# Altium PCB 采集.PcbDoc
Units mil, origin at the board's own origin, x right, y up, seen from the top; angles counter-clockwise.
Board outline 2385 x 1960 mil, 2 copper layers (Top Layer, Bottom Layer); 59 components, 37 nets, 212 pads, 27 vias.
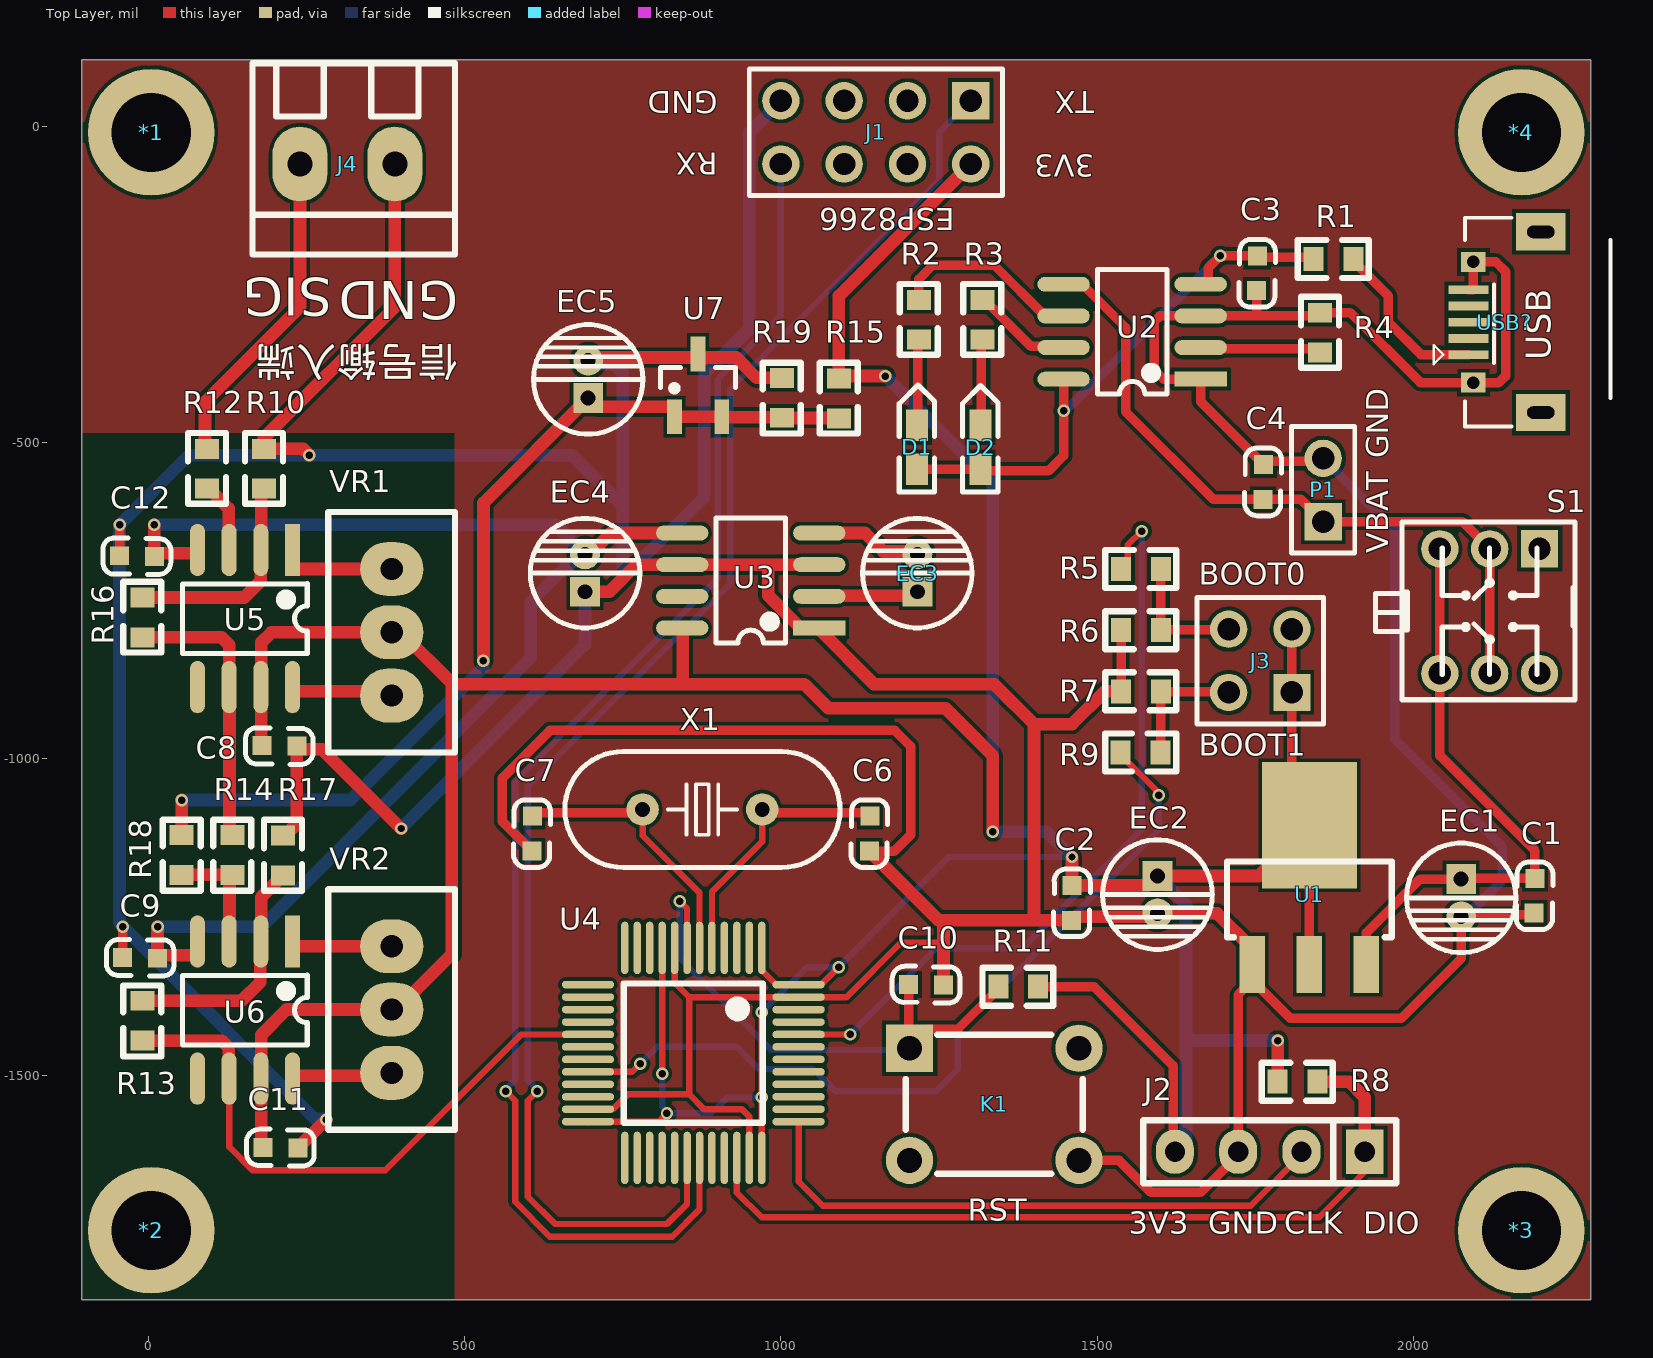
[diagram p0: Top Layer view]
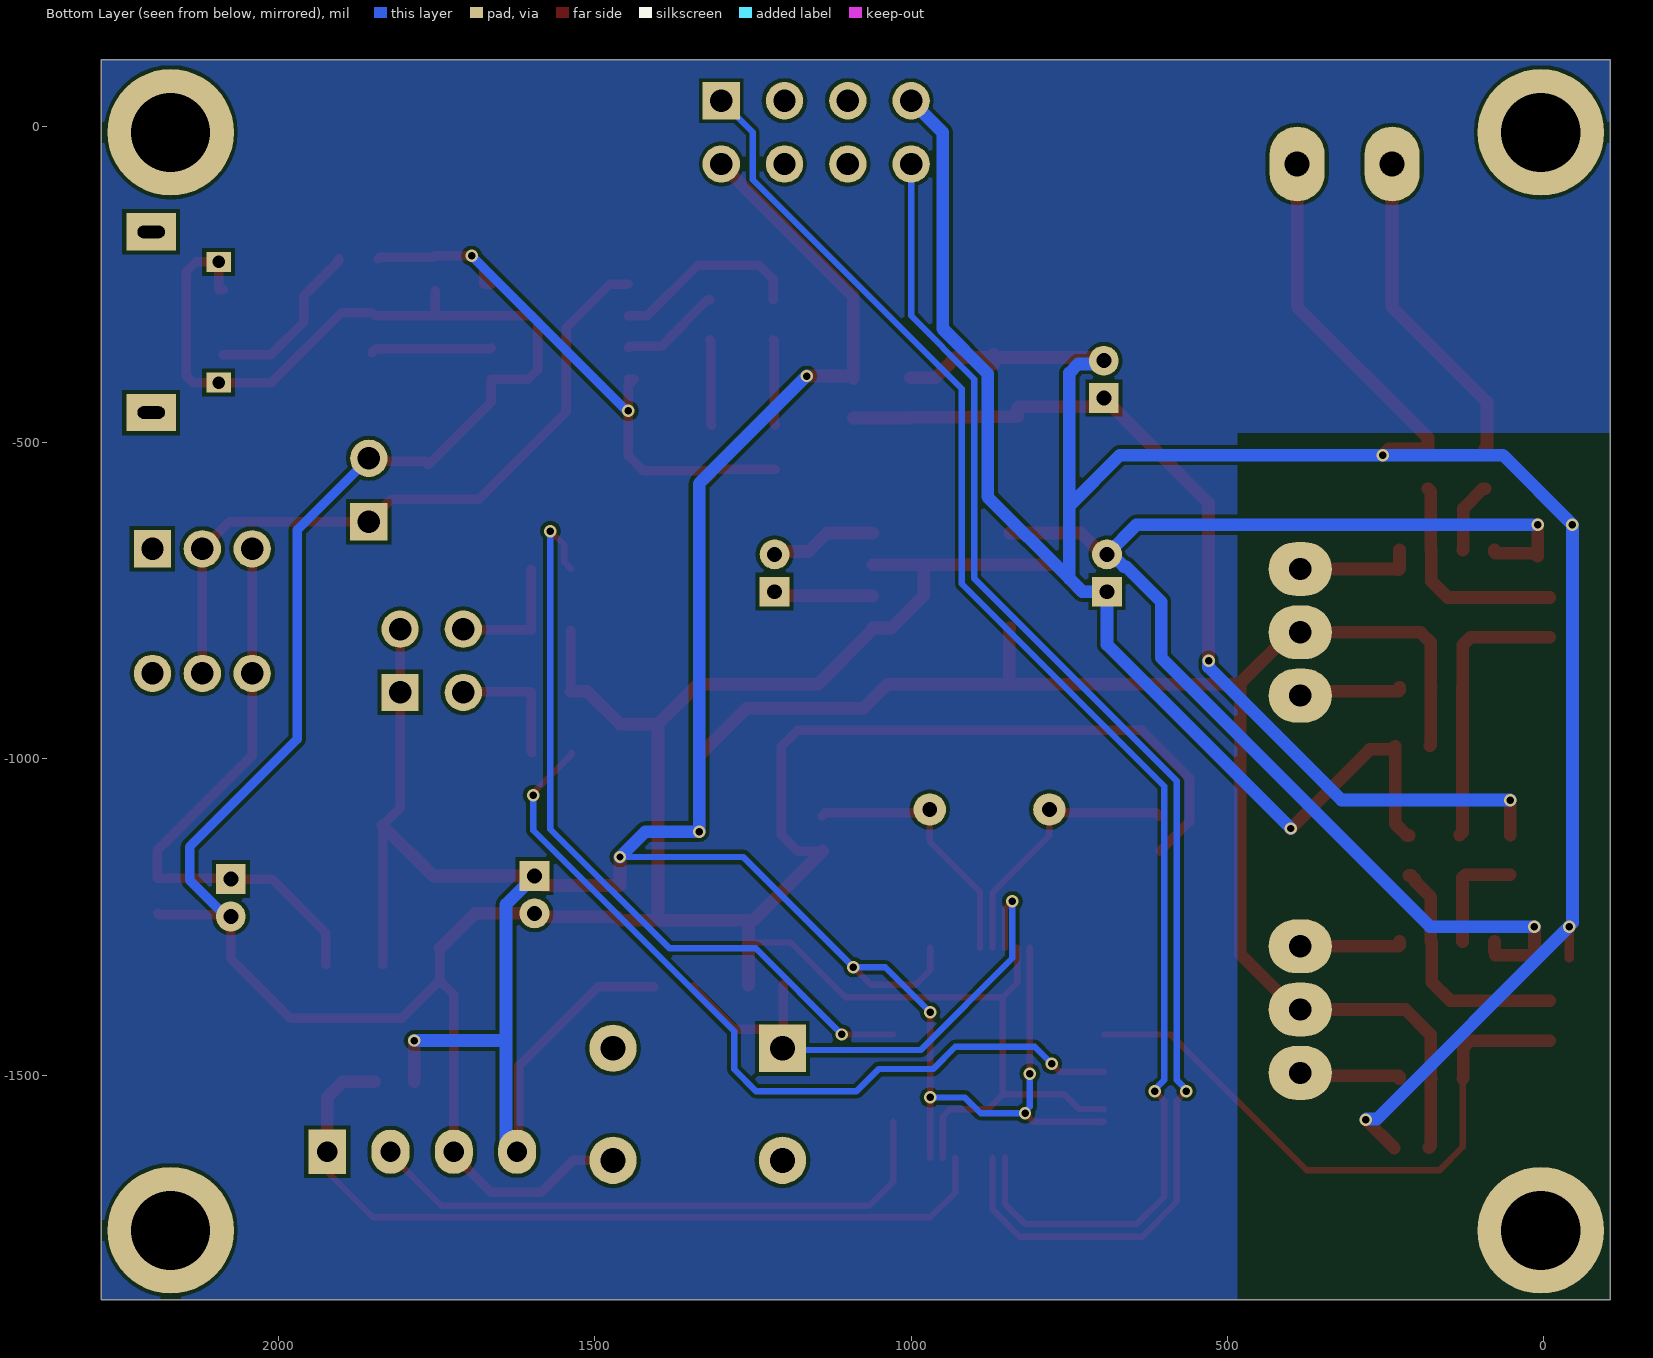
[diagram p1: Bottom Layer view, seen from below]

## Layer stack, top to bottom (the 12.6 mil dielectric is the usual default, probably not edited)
Top Solder: solder mask 0.4, Solder Resist, Dk 3.5
Top Layer: signal copper 1.4
Dielectric 1: dielectric 12.6, FR-4, Dk 4.8
Bottom Layer: signal copper 1.4
Bottom Solder: solder mask 0.4, Solder Resist, Dk 3.5

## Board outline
-105,-1855 2280,-1855 2280,105 -105,105

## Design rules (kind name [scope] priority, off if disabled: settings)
Clearance [All] p1: gap=6 ignorepadtopadclearanceinfootprint=FALSE except(0: Arc-Hole Track-Hole SMDPad-Hole THPad-Hole Via-Hole Fill-Hole Poly-Hole Region-Hole Text-Hole)
PolygonConnect [All] p1: connectstyle=Relief reliefconductorwidth=10 reliefentries=4 polygonreliefangle="90 Angle" airgapwidth=10
RoutingVias [All] p1: holewidth=28 width=50 viastyle="Through Hole" minholewidth=28 minwidth=50 maxholewidth=28 maxwidth=50
SolderMaskExpansion [All] p1: expansion=4
Width [All] p1: maxlimit=60 minlimit=10 preferedwidth=10 minimp=50.000000 maximp=50.000000 favimp=50.000000
30 further rules are at their usual default settings.

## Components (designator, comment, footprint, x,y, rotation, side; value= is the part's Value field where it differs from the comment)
*1 "*" "M3 125X200" 5,-10 r0 top
*2 "*" "M3 125X200" 5,-1745 r0 top
*3 "*" "M3 125X200" 2170,-1745 r0 top
*4 "*" "M3 125X200" 2170,-10 r0 top
C1 "CAP" 0603C 2190,-1244.06 r90 top
C2 "CAP" 0603C 1458.65,-1255.21 r90 top
C3 "106" 0603C 1751.4,-260.21 r90 top
C4 "106" 0603C 1763.11,-534.79 r270 top
C6 "22pf" 0603C 1141.02,-1090.39 r270 top
C7 "22pf" 0603C 607.93,-1090.39 r270 top
C8 "CAP" 0603C 179.79,-978.65 r0 top
C9 "CAP" 0603C 15.21,-1315.35 r180 top
C10 "100nf" 0603C 1257.06,-1357.9 r180 top
C11 "CAP" 0603C 236.79,-1615.51 r180 top
C12 "CAP" 0603C -45.21,-678.64 r0 top
D1 "LED" LED-0603G 1215.24,-542.58 r90 top
D2 "RLED" LED-0603Y 1315.24,-542.58 r90 top
EC1 "10uf" DIP-EC1.5X4X8 2075,-1190 r270 top
EC2 "10uf" DIP-EC1.5X4X8 1595,-1185 r270 top
EC3 "10uf" DIP-EC1.5X4X8 1215.55,-735.85 r90 top
EC4 "10uf" DIP-EC1.5X4X8 690.55,-735.85 r90 top
EC5 "4.7uf" DIP-EC1.5X4X8 695.55,-429.89 r90 top
J1 "*" Fe-HDR2X4/2.54-S 1300,40 r180 top
J2 "Pin HDR1X4" "Pin HDR1X4/2.54mm-S" 1922.57,-1620.76 r270 top
J3 "Pin HDR2X2" "Pin HDR2X2/2.54mm-S" 1807.54,-895 r90 top
J4 "*" KF128-3.81-2P 390,-60 r180 top
K1 "KEY" DIP-6X6X5 1203.27,-1457.19 r0 top
P1 "Header 2" HDR1X2 1856.76,-625 r90 top
R1 "1R" 0603R 1841.76,-210 r0 top
R2 "5K" 0603R 1217.99,-274.58 r270 top
R3 "5K" 0603R 1318.24,-274.58 r270 top
R4 "5K" 0603R 1851.76,-295 r270 top
R5 "10k" 0603R 1537.57,-700 r0 top
R6 "10k" 0603R 1537.57,-796.67 r0 top
R7 "10k" 0603R 1537.57,-893.33 r0 top
R8 "10k" 0603R 1785,-1510 r0 top
R9 "10k" 0603R 1599.57,-990 r180 top
R10 "20k" 0603R 183.15,-510 r270 top
R11 "10k" 0603R 1343.58,-1360 r0 top
R12 "49.9" 0603R 93.15,-510 r270 top
R13 "20k" 0603R -8.91,-1445.16 r90 top
R14 "20k" 0603R 133.15,-1183.15 r90 top
R15 "49.9" 0603R 1091.57,-398.91 r270 top
R16 "180k" 0603R -8.91,-745 r270 top
R17 "20k" 0603R 213.15,-1121.15 r270 top
R18 "20k" 0603R 53.15,-1183.15 r90 top
R19 "3k" 0603R 1001.57,-460.91 r90 top
S1 "KFT DIP-7X7" "KFT DIP-7X7" 2198.74,-668.15 r270 top
U1 "AMS1117" SOT223 1835,-1325 r0 top
U2 "TP4056X" SOP8 1663.29,-400 r180 top
U3 "tp7660" SOP8 1060.55,-793.13 r180 top
U4 "STM32F103C8T6" "LQFP48 7X7" 861.57,-1465 r180 top
U5 "OP07CDR" SOP8 228.15,-670 r270 top
U6 "OP07CDR" SOP8 228.15,-1288.62 r270 top
U7 "TL431_SMD" SOT23 831.77,-459.35 r0 top
USB? "Micro-USB" USB-micro_B 2086.57,-361.18 r90 top
VR1 "20k" 3296W 385,-800 r270 top
VR2 "20k" 3296W 385,-1396.1 r90 top
X1 "XTAL-2P" "OSC HC-49S" 876.06,-1080 r0 top

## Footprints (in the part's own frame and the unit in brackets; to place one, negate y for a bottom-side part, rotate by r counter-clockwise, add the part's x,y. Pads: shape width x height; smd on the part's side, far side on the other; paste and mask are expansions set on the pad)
0603C [mil]
  rect 30x30 smd: 1(0.21,-0.35) 2(55.21,-1.35)
  silkscreen extent -26,-30 81,28, body extent -1,-15 62,17, height 12
0603R [mm]
  rect 0.8x0.965 smd: 1(0,0) 2(1.6,0)
  silkscreen extent -0.63,-0.76 2.21,0.76, body extent -0.04,-0.41 1.56,0.41, height 0.45
3296W [mil]
  oval 85x100 hole 35: 1(-100,0) 2(0,0) 3(100,0)
  silkscreen extent -190,-100 190,100, body extent -188,-94 188,94, height 455
DIP-6X6X5 [mm]
  rect 1.9x1.9 hole 1: 1(0,0)
  round 1.9 hole 1: 2(0,-4.5) 3(6.8,-4.5) 4(6.8,0)
  silkscreen extent -0.16,-5.04 6.96,0.54, body extent -0.8,-5.24 7.41,0.76, height 4.95
DIP-EC1.5X4X8 [mm]
  rect 1.2x1.2 hole 0.6: 1(0,0)
  round 1.2 hole 0.6: 2(1.5,0)
  silkscreen extent -1.45,-2.2 2.95,2.2, body extent -1.26,-1.97 2.76,2.03, height 8.04
Fe-HDR2X4/2.54-S [mm] "Connector; Header; 4x2 Position"
  rect 1.5x1.5 hole 0.9: 1(0,0)
  round 1.5 hole 0.9: 2(0,2.54) 3(2.54,0) 4(2.54,2.54) 5(5.08,0) 6(5.08,2.54) 7(7.62,0) 8(7.62,2.54)
  silkscreen extent -1.27,-1.27 8.89,3.81, body extent -1.27,-1.23 9.14,3.77, height 8.5
HDR1X2 [mm] "Connector; Header; 2 Position"
  rect 1.5x1.5 hole 0.9: 1(0,0)
  round 1.5 hole 0.9: 2(2.54,0)
  silkscreen extent -1.27,-1.27 3.81,1.27
KF128-3.81-2P [mm] "螺钉式接线端子，脚距3.81mm"
  oval 2.2x3 hole 1: 1(0,0) 2(3.81,0)
  silkscreen extent -2.41,-4.04 5.72,3.63, body extent -2.41,-3.83 5.71,3.57, height 8.55
"KFT DIP-7X7" [mm]
  rect 1.5x1.5 hole 0.9: 1(0,0)
  round 1.5 hole 0.9: 2(0,-2) 3(0,-4) 4(5,-4) 5(5,-2) 6(5,0)
  silkscreen extent -1.08,-6.58 6.06,1.42, body extent -1.09,-5.46 5.91,1.54, height 11.2
LED-0603G [mil]
  rect 50x35 smd: A(0,0.26) K(70,0.26)
  silkscreen extent -36,-28 134,28, body extent 4,-15 66,17, height 24
LED-0603Y [mil]
  rect 50x35 smd: A(0,0) K(70,0)
  silkscreen extent -36,-28 133,28, body extent 4,-17 66,15, height 24
"LQFP48 7X7" [mm]
  oval 0.3x2.1 smd: 1(-2.75,-4.227) 2(-2.25,-4.227) 3(-1.75,-4.227) 4(-1.25,-4.227) 5(-0.75,-4.227) 6(-0.25,-4.227) 7(0.25,-4.227) 8(0.75,-4.227) 9(1.25,-4.227) 10(1.75,-4.227) 11(2.25,-4.227) 12(2.75,-4.227) 25(2.75,4.202) 26(2.25,4.202) 27(1.75,4.202) 28(1.25,4.202) 29(0.75,4.202) 30(0.25,4.202) 31(-0.25,4.202) 32(-0.75,4.202) 33(-1.25,4.202) 34(-1.75,4.202) 35(-2.25,4.202) 36(-2.75,4.202)
  oval 2.1x0.3 smd: 13(4.227,-2.75) 14(4.227,-2.25) 15(4.227,-1.75) 16(4.227,-1.25) 17(4.227,-0.75) 18(4.227,-0.25) 19(4.227,0.25) 20(4.227,0.75) 21(4.227,1.25) 22(4.227,1.75) 23(4.227,2.25) 24(4.227,2.75) 37(-4.227,2.75) 38(-4.227,2.25) 39(-4.227,1.75) 40(-4.227,1.25) 41(-4.227,0.75) 42(-4.227,0.25) 43(-4.227,-0.25) 44(-4.227,-0.75) 45(-4.227,-1.25) 46(-4.227,-1.75) 47(-4.227,-2.25) 48(-4.227,-2.75)
  silkscreen extent -2.79,-2.79 2.79,2.79, body extent -4.51,-4.5 4.5,4.5, height 1.45
"M3 125X200" [mil] "M3螺丝孔，孔125Mil，焊盘200Mil"
  round 200 hole 125: 1(0,0)
"OSC HC-49S" [mm]
  round 1.3 hole 0.6: 1(-2.4,0) 2(2.4,0)
  silkscreen extent -5.52,-2.32 5.52,2.33, body extent -5.53,-2.29 5.53,2.36, height 4.13
"Pin HDR1X4/2.54mm-S" [mil]
  rect 70x60 hole 32: 1(0,0)
  oval 70x60 hole 32: 2(0,-100) 3(0,-200) 4(0,-300)
  silkscreen extent -50,-350 50,50, body extent -50,-350 50,50, height 336
"Pin HDR2X2/2.54mm-S" [mm] "Connector; Header; 2x2 Position"
  rect 1.5x1.5 hole 0.9: 1(0,0)
  round 1.5 hole 0.9: 2(0,2.54) 3(2.54,0) 4(2.54,2.54)
  silkscreen extent -1.27,-1.27 3.81,3.81, body extent -1.27,-1.27 3.81,3.81, height 7.58
SOP8 [mm]
  rect 2.1x0.6 smd: 1(0,0)
  oval 2.1x0.6 smd: 2(0,-1.27) 3(0,-2.54) 4(0,-3.81) 5(5.5,-3.81) 6(5.5,-2.54) 7(5.5,-1.27) 8(5.5,0)
  silkscreen extent 1.35,-4.41 4.15,0.6, body extent -0.21,-4.44 5.8,0.56, height 1.9
SOT23 [mm]
  rect 0.6x1.4 smd: D(0.95,2.514) G(0,0) S(1.9,0)
  silkscreen extent -0.55,1.02 2.45,1.97, body extent -0.56,0.22 2.44,2.62, height 1.05
SOT223 [mil]
  rect 40x90 smd: 1(-90,0) 2(0,0) 3(90,0)
  rect 150x200 smd: 2(0,220)
  silkscreen extent -130,43 130,163, body extent -130,-30 126,246, height 65
USB-micro_B [mm]
  rect 1.5x2 hole 0.5 slot 1.1 at 90 deg: 0(-2.325,-2.9) 0(4.925,-2.9)
  rect 0.35x1.6 smd: 1(0,0) 2(0.65,0) 3(1.3,0) 4(1.95,0) 5(2.6,0)
  rect 0.8x1 hole 0.5: 5(-1.125,-0.19) 5(3.725,-0.19)
  silkscreen extent -2.89,-5.69 5.49,1.4, body extent -2.7,-5.6 5.3,0, height 2.8

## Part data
*1 *2 *3 *4: library part M3, "铜柱孔"
C1 C2 C8 C9 C11 C12: "无极性电容"
C3 C4 C6 C7 C10: library part CAP, "无极性电容"
D2: library part LED
EC1 EC2 EC3 EC4 EC5: library part DIP_ECAP, "直插电解电容"
J1: library part "Female HDR2X4"
J4: library part KF128-2P
P1: "Header, 2-Pin"
R1 R2 R3 R4 R5 R6 R7 R8 R9 R10 R11 R12 R13 R14 R15 R16 R17 R18 R19: library part RES
U1: "三端稳压芯片"
U2: library part TP4056
U4: BOM_JLCPCB Part Class="Basic Part", BOM_Manufacturer=STMicroelectronics
U5 U6: library part op07cdr
U7: "可调基准稳压芯片"
VR1 VR2: library part RESVR
X1: "2脚无源脚晶振"

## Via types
v1: diameter 19.68, hole 11.81, Top Layer to Bottom Layer, 27 vias

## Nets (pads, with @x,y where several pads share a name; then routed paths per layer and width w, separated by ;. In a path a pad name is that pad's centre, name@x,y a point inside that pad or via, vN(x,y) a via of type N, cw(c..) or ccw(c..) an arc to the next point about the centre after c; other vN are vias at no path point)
2v5: EC5.1 R15.2 R18.2 R19.1 U7.G U7.S | length 1530.2
  Top Layer w20: R18.2 v1(53.15,-1065) ; v1(530,-845) 530,-595.44 EC5.1 709.17,-443.51 829.96,-443.51 831.77,-445.32 U7.G U7.S 907.35,-460.13 1000.8,-460.13 R19.1 1002.07,-461.41 1091.08,-461.41 R15.2
  Bottom Layer w20: v1(53.15,-1065) 320,-1065 530,-855 v1(530,-845)
3V3: C2.2 C8.1 C11.2 EC2.1 J1.2 J2.4 J3.1 J3.3 R8.1 R11.2 R15.1 U1.2 U3.8 U4.1 U4.9 U4.24 U4.36 U4.48 U5.7 U6.7 VR1.2 VR2.2 | length 7640.9
  Top Layer w10: U4.24@696.57,-1574.1 695.74,-1573.27 806.73,-1573.27 v1(820,-1560) ; v1(812.36,-1497.36) U4.9 ; U4.36 v1(969.84,-1535) v1(969.84,-1400.34) ; U4.1 969.84,-1334.02 992.56,-1356.73 U4.48 1063.43,-1356.73 v1(1091.08,-1329.08)
  Top Layer w15: R11.2 1495,-1360 1620,-1485 1620,-1618.18 J2.4 ; EC2.1@1580,-1200 EC2.1 ; J3.3 J3.1 1807.54,-1077.54 1835,-1105 U1.2@1835,-1325
  Top Layer w20: C8.1 178.84,-977.84 178.84,-887.23 U5.7 178.84,-885.84 178.84,-816.16 195,-800 VR1.2 400,-800 481.99,-881.99 ; C11.2 178.84,-1611.43 178.84,-1505.85 U6.7 178.84,-1504.46 178.84,-1436.16 218.9,-1396.1 VR2.2 392.5,-1396.1 480,-1308.6 480,-881.99 481.99,-881.99 ; U3.8 845,-794.12 845,-881.99 ; v1(1165,-395) 1095.49,-395 R15.1 1091.57,-268.43 J1.2 ; v1(1335,-1115) 1335,-995 1260,-920 1075,-920 1036.99,-881.99 845,-881.99 ; v1(1460,-1155) C2.2 EC2.1@1580,-1200 ; EC2.1 1755,-1185 U1.2@1835,-1105 ; R8.1 v1(1785,-1445) ; 481.99,-881.99 845,-881.99
  Bottom Layer w10: v1(812.36,-1497.36) 812.36,-1549.74 820,-1557.38 v1(820,-1560) 890,-1560 915,-1535 v1(969.84,-1535) ; v1(969.84,-1400.34) 969.84,-1400.16 1040.92,-1329.08 v1(1091.08,-1329.08) 1265.16,-1155 v1(1460,-1155)
  Bottom Layer w15: J2.4 J2.4@1640,-1603.33
  Bottom Layer w20: v1(1165,-395) 1335,-565 v1(1335,-1115) 1420,-1115 v1(1460,-1155) ; EC2.1 1640,-1230 1640,-1445 ; J2.4@1640,-1603.33 1640,-1445 ; v1(1785,-1445) 1640,-1445
+5: R1.2 USB?.1 | length 270.7
  Top Layer w15: R1.2 1904.75,-213.25 1960,-268.5 1960,-310 2011.18,-361.18 USB?.1
-3V3: C9.1 C12.2 EC4.2 U3.5 U5.4 U6.4 | length 2098.2
  Top Layer w20: v1(10,-630) C12.2 15,-675 76.48,-675 78.15,-673.33 U5.4 ; v1(15,-1265) C9.1 20,-1310 76.48,-1310 76.48,-1305.16 78.15,-1303.48 U6.4 ; EC4.2 697.92,-676.79 731.58,-643.13 U3.5
  Bottom Layer w20: v1(10,-630) 643.76,-630 EC4.2 683.18,-676.79 663.75,-696.23 660.3,-696.23 605,-751.53 605,-840 180,-1265 v1(15,-1265)
GND: C1.1 C2.1 C3.1 C4.1 C6.2 C7.2 C8.2 C9.2 C10.1 C11.1 C12.1 EC1.2 EC2.2 EC4.1 EC5.2 J1.7 J2.3 J4.1 K1.2 K1.3 P1.2 R4.1 R6.1 R7.1 R10.1 R17.1 R19.2 U1.1 U2.1 U2.3 U3.1 U3.3 U3.6 U4.8 U4.23 U4.35 U4.47 U7.D USB?.5 | length 13036.4
  Top Layer w10: U4.23 695.5,-1553.24 735.16,-1553.24 758.4,-1530 855,-1530 ; U4.8 832.39,-1298.93 832.39,-1353.81 855,-1376.42 ; U4.35 950.16,-1565.16 938.58,-1553.58 878.58,-1553.58 855,-1530 ; 1256.84,-1290 1190,-1290 1103.58,-1376.42 U4.47 855,-1376.42 ; 855,-1530 855,-1376.42
  Top Layer w15: C12.1 v1(-45,-630) ; C9.2 v1(-40,-1265) ; C7.2 560,-1099.03 560,-1030 635,-955 1180,-955 1205,-980 1205,-1120 1179.4,-1145.6 C6.2 ; 1256.84,-1263.16 1265,-1255 ; C2.1 C2.1@1464.47,-1249.53 ; K1.3 1534.35,-1634.35 1585,-1685 1663.33,-1685 1722.57,-1625.76 J2.3 1722.57,-1372.43 U1.1@1745,-1350 ; R7.1 R6.1 ; EC2.2@1589.53,-1249.53 EC2.2 ; U1.1@1745,-1300 U1.1 U1.1@1745,-1350 ; C3.1 1751.76,-300 ; P1.2 1851.76,-530 1767.76,-530 C4.1 1663.29,-435.54 U2.1 1605,-400 1590,-385 1590,-308.79 1598.79,-300 U2.3 1751.76,-300 ; USB?.5@2086.57,-258.82 2093.44,-258.82 2094.06,-258.21 2094.06,-214.53 2129.53,-214.53 2145,-230 2145,-395 2134.53,-405.47 2094.06,-405.47 2010.47,-405.47 1900,-295 R4.1 1846.76,-300 1751.76,-300 ; C1.1 2187.75,-1246.45 2077.61,-1246.45 EC1.2 2075,-1315.16 1980.16,-1410 1805,-1410 U1.1@1745,-1350
  Top Layer w20: R17.1 216.4,-1121.15 235,-1102.55 C8.2 240,-985 275,-985 v1(400,-1110) ; C11.1 v1(281.73,-1570) ; v1(255,-520) 245,-510 R10.1 183.15,-492.6 390,-285.75 ; 390,-280 J4.1 ; EC4.1 729.15,-735.85 771.87,-693.13 U3.6 980,-693.13 ; EC5.2 700.76,-365.62 867.37,-365.62 U7.D@869.18,-363.81 ; U7.D U7.D@869.18,-363.81 ; R19.2 961.74,-397.92 929.44,-365.62 879.69,-365.62 869.18,-376.13 U7.D@869.18,-363.81 ; U3.1@1060,-795 1146.99,-881.99 1336.99,-881.99 1400,-945 ; U3.1 1031.02,-793.13 980,-742.11 980,-693.13 ; U3.3 980,-693.13 ; C6.2 1249.06,-1255 1265,-1255 1400,-1255 ; C10.1 1256.84,-1290 1256.84,-1263.16 ; C2.1 1400,-1255 ; C2.1@1464.47,-1249.53 EC2.2@1589.53,-1249.53 ; R7.1 1511.67,-893.33 1460,-945 1400,-945 ; EC2.2 1689.06,-1244.06 U1.1@1745,-1300 ; 1400,-1255 1400,-945
  Bottom Layer w15: v1@-45,-1258.73 -40,-1263.73 v1(-40,-1265) ; v1@280.84,-1569.1 v1(281.73,-1570) ; P1.2 1970,-638.24 1970,-968.74 2140,-1138.74 2140,-1191.34 2082.28,-1249.06 EC1.2
  Bottom Layer w20: v1@-45,-1258.73 v1(-45,-630) 65,-520 v1(255,-520) 670,-520 750,-600 ; v1(-40,-1265) 264.1,-1569.1 v1@280.84,-1569.1 ; v1(400,-1110) 690.55,-819.45 EC4.1 729.15,-735.85 750,-715 ; EC5.2 700.76,-376.05 736.05,-376.05 750,-390 750,-600 ; J1.7 950,-10 950,-320.3 879,-391.3 879,-586 750,-715 ; 750,-715 750,-600
NetC1_2: C1.2 EC1.1 S1.3 S1.4 U1.3 | length 934.9
  Top Layer w15: U1.3 1925,-1275 2010,-1190 EC1.1 2076.16,-1188.84 C1.2 2191.35,-1144.78 2041.26,-994.68 S1.4 S1.3
NetC3_2: C3.2 D1.A D2.A R1.1 U2.4 U2.8 | length 965.3
  Top Layer w15: D1.A D2.A 1315.24,-550 1325.24,-560 1325.24,-545 1422.84,-545 1446.76,-521.09 v1(1446.76,-450) 1446.76,-408.91 1437.84,-400 U2.8 ; U2.4 1675,-250 1675,-224.53 v1(1694.53,-205) C3.2 1755.26,-207.5 1839.26,-207.5 R1.1
  Bottom Layer w15: v1(1446.76,-450) 1447.65,-449.1 1450.42,-449.1 v1(1694.53,-205)
NetC4_2: C4.2 P1.1 S1.2 S1.5 U2.5 | length 1121.2
  Top Layer w15: U2.5 1476.28,-250 1545,-318.72 1545,-451.71 1683.29,-590 C4.2 1821.76,-590 P1.1 1856.88,-625.12 2076.97,-625.12 S1.2 S1.5
NetC6_1: C6.1 U4.5 X1.2 | length 426
  Top Layer w10: U4.5 891.1,-1210 970.55,-1130.55 X1.2
  Top Layer w15: X1.2 975.85,-1085.3 1135.36,-1085.3 C6.1
NetC7_1: C7.1 U4.6 X1.1 | length 434.2
  Top Layer w10: X1.1 781.57,-1121.57 871.42,-1211.42 U4.6
  Top Layer w15: C7.1 612.88,-1085.3 776.27,-1085.3 X1.1
NetC10_2: C10.2 K1.1 K1.4 R11.1 U4.7 | length 876.6
  Top Layer w10: v1(840,-1225) 851.73,-1236.73 U4.7
  Top Layer w15: C10.2 1201.84,-1455.77 K1.1 1233.17,-1427.29 1279.54,-1427.29 1343.58,-1363.25 R11.1
  Bottom Layer w10: v1(840,-1225) 840,-1315 985,-1460 1200.46,-1460 K1.1
NetD1_K: D1.K R2.2 | length 136.2
  Top Layer w15: D1.K 1216.49,-471.07 1216.49,-339.07 R2.2
NetD2_K: D2.K R3.2 | length 136.2
  Top Layer w15: D2.K 1316.74,-471.07 1316.74,-339.07 R3.2
NetEC3_1: EC3.1 U3.2 | length 158
  Top Layer w20: U3.2 1061.24,-742.44 1208.96,-742.44 EC3.1
NetEC3_2: EC3.2 U3.4 | length 168.9
  Top Layer w20: U3.4 1132.79,-643.13 1161.93,-672.27 1211.03,-672.27 EC3.2
NetJ1_1: J1.1 U4.30 | length 2389.8
  Top Layer w10: v1(615,-1525) 600,-1540 600,-1691.73 643.27,-1735 820,-1735 851.73,-1703.27 U4.30
  Bottom Layer w10: v1(615,-1525) 615,-1522.38 600,-1507.38 600,-1043.28 920,-723.28 920,-415 1250,-85 1250,-10 J1.1
NetJ1_8: J1.8 U4.31 | length 2239.9
  Top Layer w10: v1(565,-1525) 580,-1540 580,-1700 634.99,-1754.99 828.28,-1754.99 871.42,-1711.85 U4.31
  Bottom Layer w10: v1(565,-1525) 565,-1522.38 580,-1507.38 580,-1035 900,-715 900,-400 1000,-300 J1.8
NetJ2_1: J2.1 R8.2 U4.34 | length 1295.5
  Top Layer w10: U4.34 930.47,-1685.47 969.5,-1724.5 1850.5,-1724.5 1922.57,-1652.43 J2.1
  Top Layer w20: R8.2 1897.57,-1510 1922.57,-1535 J2.1
NetJ2_2: J2.2 U4.37 | length 943.3
  Top Layer w10: U4.37 1027.99,-1667.99 1066,-1706 1742.33,-1706 1822.57,-1625.76 J2.2
NetJ3_2: J3.2 R7.2 R9.1 | length 204.3
  Top Layer w15: R9.1 1600.06,-989.5 1600.06,-893.83 1600.4,-894.17 1706.71,-894.17 J3.2
NetJ3_4: J3.4 R5.2 R6.2 | length 204.3
  Top Layer w15: R5.2 R6.2 1601.39,-795.83 1706.71,-795.83 J3.4
NetJ4_2: J4.2 R12.1 | length 513.4
  Top Layer w20: R12.1 90,-506.85 90,-435.75 240,-285.75 J4.2
NetR2_1: R2.1 U2.6 | length 303.6
  Top Layer w15: R2.1 1217.99,-242.01 1240,-220 1337.23,-220 1417.23,-300 U2.6
NetR3_1: R3.1 U2.7 | length 159.8
  Top Layer w15: R3.1 1321.49,-274.58 1395.26,-348.35 1445.11,-348.35 U2.7
NetR4_2: R4.2 U2.2 | length 191.8
  Top Layer w15: U2.2 1664.94,-351.65 1845.41,-351.65 R4.2
NetR5_1: R5.1 U4.44 | length 1220.8
  Top Layer w10: U4.44 v1(1109.32,-1435.47) ; R5.1 1548.31,-689.25 1548.31,-661.69 v1(1570,-640)
  Bottom Layer w10: v1(1109.32,-1435.47) 1245.48,-1299.31 1381.67,-1299.31 1570,-1110.98 v1(1570,-640)
NetR9_2: R9.2 U4.20 | length 1301.2
  Top Layer w10: U4.20 765.31,-1494.53 v1(778.01,-1481.83) ; R9.2 1536.57,-993.25 1595.35,-1052.02 1595.35,-1055.35 v1(1597.2,-1057.2)
  Bottom Layer w10: v1(778.01,-1481.83) 804.84,-1455 930,-1455 965,-1490 1051.21,-1490 1086.21,-1525 1245,-1525 1279.54,-1490.46 1279.54,-1430.46 1597.2,-1112.8 v1(1597.2,-1057.2)
NetR10_2: R10.2 R16.1 U5.2 | length 345.8
  Top Layer w20: R16.1 151.99,-745 178.15,-718.84 U5.2 178.84,-669.31 178.84,-577.3 R10.2
NetR12_2: R12.2 U5.3 | length 113.4
  Top Layer w20: R12.2 96.4,-572.99 127.46,-604.05 127.46,-669.31 U5.3
NetR13_1: R13.1 U4.17 U6.6 | length 969.3
  Top Layer w10: U6.6 128.15,-1613.15 165,-1650 375,-1650 589.53,-1435.47 U4.17
  Top Layer w20: R13.1 116.43,-1445.16 127.46,-1456.18 127.46,-1504.46 U6.6
NetR13_2: R13.2 R17.2 U6.2 | length 383.7
  Top Layer w20: R13.2 147.83,-1382.17 177.46,-1352.54 177.46,-1289.32 U6.2 178.84,-1287.93 178.84,-1218.45 204.15,-1193.14 204.15,-1189.89 209.9,-1184.14 R17.2
NetR14_1: R14.1 R18.1 U6.3 | length 178.9
  Top Layer w20: R18.1 124.54,-1183.15 128.84,-1187.46 128.84,-1287.93 U6.3
NetR14_2: R14.2 R16.2 U5.6 | length 444.4
  Top Layer w20: R16.2 116.43,-807.99 128.15,-819.71 U5.6 128.84,-887.23 128.84,-1115.85 R14.2
NetU5_1: U5.1 VR1.1 | length 188.4
  Top Layer w20: U5.1@228.15,-699.53 U5.1@229.96,-701.34 ; U5.1 228.15,-698.19 229.96,-700 VR1.1
NetU5_8: U5.8 VR1.3 | length 165.4
  Top Layer w20: U5.8 228.15,-891.59 229.82,-893.27 378.27,-893.27 VR1.3
NetU6_1: U6.1 VR2.3 | length 163.3
  Top Layer w20: U6.1 228.15,-1294.29 229.96,-1296.1 VR2.3
NetU6_8: U6.8 VR2.1 | length 162.3
  Top Layer w20: U6.8 228.15,-1502.3 229.82,-1500.63 380.47,-1500.63 VR2.1
pads on no net: *1.1 *2.1 *3.1 *4.1 J1.3 J1.4 J1.5 J1.6 S1.1 S1.6 U3.7 U4.2 U4.3 U4.4 U4.10 U4.11 U4.12 U4.13 U4.14 U4.15 U4.16 U4.18 U4.19 U4.21 U4.22 U4.25 U4.26 U4.27 U4.28 U4.29 U4.32 U4.33 U4.38 U4.39 U4.40 U4.41 U4.42 U4.43 U4.45 U4.46 U5.5 U6.5 USB?.0 USB?.2 USB?.3 USB?.4

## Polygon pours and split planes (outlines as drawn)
no net on Top Layer (solid, pour order 14): -105,105 -105,-485 485,-485 485,-1855 2280,-1855 2280,105
no net on Bottom Layer (solid, pour order 16): -105,105 -105,-485 485,-485 485,-1855 2280,-1855 2280,105

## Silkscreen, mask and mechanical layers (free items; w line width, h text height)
Top Overlay:
  text "GND" at 900,55 h35 r180
  text "TX" at 1495,55 h35 r180
  text "RX" at 900,-42.08 h35 r180
  text "3V3" at 1495,-45 h35 r180
  text "ESP8266" at 1275,-130 h35 r180
  text "SIG" at 290,-240 h60 r180
  text "GND" at 490,-245 h60 r180
  text "信号输入端" at 490,-334.89 h80 r180
  text "GND" at 1960,-525 h35 r90
  text "VBAT" at 1960,-675 h35 r90
  text "BOOT0" at 1660,-725 h35
  text "BOOT1" at 1660,-995 h35
  text "RST" at 1295,-1730 h35
  text "3V3" at 1550,-1750 h35
  text "GND" at 1675,-1750 h35
  text "CLK" at 1795,-1750 h35
  text "DIO" at 1920,-1750 h35
Mechanical 1:
  the board outline again, w10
